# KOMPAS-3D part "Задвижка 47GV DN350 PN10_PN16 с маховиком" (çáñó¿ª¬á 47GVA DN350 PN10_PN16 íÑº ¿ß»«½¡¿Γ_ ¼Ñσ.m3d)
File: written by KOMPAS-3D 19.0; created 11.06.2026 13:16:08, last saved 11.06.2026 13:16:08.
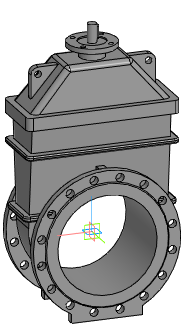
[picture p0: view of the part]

Document properties: Автор: Евгений; Полное имя файла: Z:\3.Личные\kachalov\001_3d для проектировщиков\2.2 Тип 47GVA, 47GVA.Z\_stp\_stp_Задвижка 47GVA DN40-DN1000 без исп.мех\Задвижка 47GVA DN350 PN10_PN16 без исполнит_ мех.m3d

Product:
- Part/product: Задвижка 47GV DN350 PN10_PN16 с маховиком

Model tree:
1. Операция без истории:1  (labels: Задвижка 47GV DN350 PN10_PN16 с маховиком)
